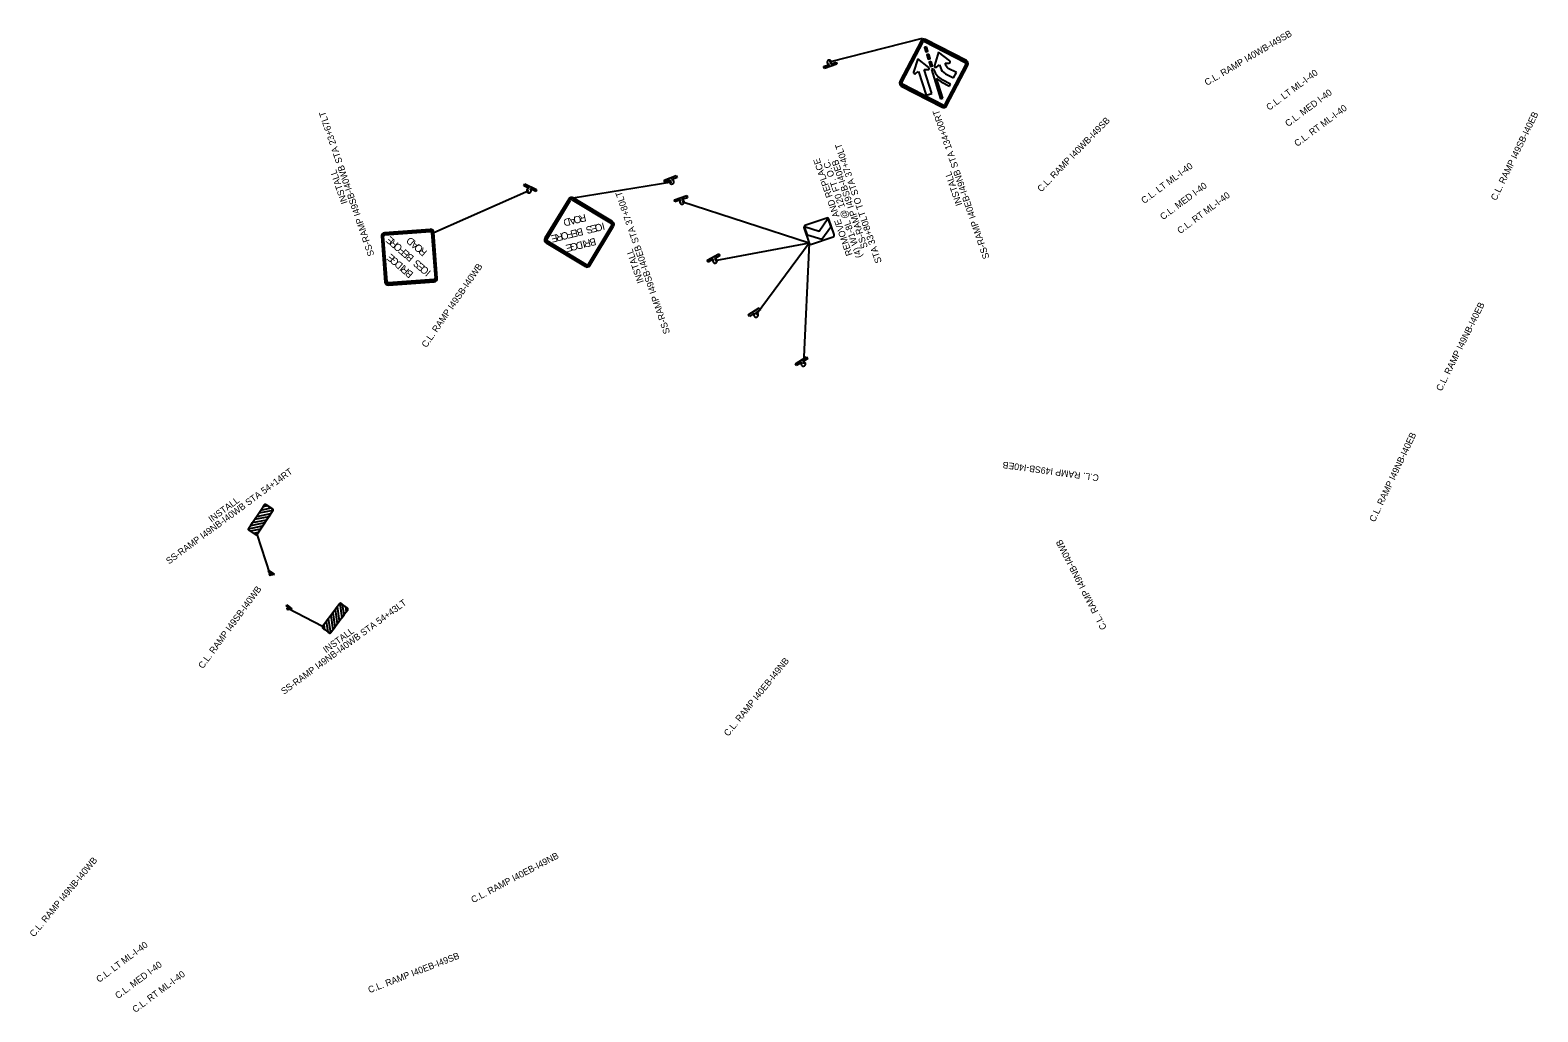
# Model space of a CAD drawing. Extents: x 639753 to 654136, y 407791 to 434220.
# Drawn here: x 643443 to 646199, y 424993 to 426786 of the extents above; entities that cross this region are included whole.
import ezdxf

# ---------------------------------------------------------------- set-up
doc = ezdxf.new("R2010")
doc.units = 0
for name, color, linetype in [('C-TRAF-SYMB', 7, 'Continuous'), ('P_SIGN_SR', 7, 'Continuous'), ('R_Anno_Text', 7, 'Continuous'), ('R_Dimension', 7, 'Continuous'), ('S_SIGN', 7, 'Continuous')]:
    doc.layers.add(name, color=color, linetype=linetype)

msp = doc.modelspace()

# ---------------------------------------------------------------- linework, layer by layer
at = {"layer": 'C-TRAF-SYMB'}
for p, q in [((644893.5, 426720.3), (644904.1, 426723.8)), ((644894.8, 426716.5), (644893.5, 426720.3)), ((644917.6, 426724.1), (644894.8, 426716.5)), ((644904.1, 426723.8), (644904.1, 426723.9)), ((644905.8, 426724.4), (644916.3, 426727.9)), ((644905.8, 426724.5), (644905.8, 426724.4)), ((644916.3, 426727.9), (644917.6, 426724.1)), ((644345.4, 426501.8), (644347.1, 426505.4)), ((644355.5, 426497.2), (644345.4, 426501.8)), ((644347.1, 426505.4), (644368.9, 426495.5)), ((644355.4, 426497.1), (644355.5, 426497.2)), ((644367.3, 426491.9), (644357.1, 426496.5)), ((644357.1, 426496.5), (644357.1, 426496.4)), ((644368.9, 426495.5), (644367.3, 426491.9)), ((644601.9, 426512.2), (644624.2, 426521.1)), ((644603.3, 426508.5), (644601.9, 426512.2)), ((644613.6, 426512.6), (644603.3, 426508.5)), ((644613.6, 426512.5), (644613.6, 426512.6)), ((644625.6, 426517.3), (644615.3, 426513.2)), ((644615.3, 426513.2), (644615.3, 426513.1)), ((644624.2, 426521.1), (644625.6, 426517.3)), ((644620.6, 426476.4), (644643.3, 426484.1)), ((644621.8, 426472.6), (644620.6, 426476.4)), ((644632.3, 426476.1), (644621.8, 426472.6)), ((644632.3, 426476), (644632.3, 426476.1)), ((644644.6, 426480.3), (644634, 426476.7)), ((644634, 426476.7), (644634.1, 426476.6)), ((644643.3, 426484.1), (644644.6, 426480.3)), ((644680.5, 426366.2), (644701.8, 426377.4)), ((644682.4, 426362.7), (644680.5, 426366.2)), ((644692.2, 426367.8), (644682.4, 426362.7)), ((644692.2, 426367.7), (644692.2, 426367.8)), ((644703.6, 426373.8), (644693.8, 426368.6)), ((644693.8, 426368.6), (644693.8, 426368.6)), ((644701.8, 426377.4), (644703.6, 426373.8)), ((644755.7, 426266.3), (644775.9, 426279.3)), ((644778, 426276), (644768.7, 426269.9)), ((644775.9, 426279.3), (644778, 426276)), ((644757.8, 426263), (644755.7, 426266.3)), ((644767.1, 426269), (644757.8, 426263)), ((644767.2, 426268.9), (644767.1, 426269)), ((644768.7, 426269.9), (644768.7, 426269.9)), ((644842.1, 426176.7), (644862.2, 426189.7)), ((644844.2, 426173.4), (644842.1, 426176.7)), ((644853.5, 426179.3), (644844.2, 426173.4)), ((644853.6, 426179.2), (644853.5, 426179.3)), ((644864.4, 426186.3), (644855, 426180.3)), ((644855, 426180.3), (644855.1, 426180.2)), ((644862.2, 426189.7), (644864.4, 426186.3)), ((643878, 425797.6), (643879.2, 425799.3)), ((643882.6, 425794.4), (643878, 425797.6)), ((643879.2, 425799.3), (643889, 425792.4)), ((643882.5, 425794.4), (643882.6, 425794.4)), ((643887.9, 425790.7), (643883.3, 425793.9)), ((643883.3, 425793.9), (643883.3, 425793.9)), ((643889, 425792.4), (643887.9, 425790.7)), ((643910.9, 425734.9), (643912.2, 425736.5)), ((643915.2, 425731.5), (643910.9, 425734.9)), ((643912.2, 425736.5), (643921.5, 425729)), ((643915.2, 425731.4), (643915.2, 425731.5)), ((643920.3, 425727.4), (643915.9, 425730.9)), ((643915.9, 425730.9), (643915.9, 425730.9)), ((643921.5, 425729), (643920.3, 425727.4))]:
    msp.add_line(p, q, dxfattribs=at)
for centre, radius, start, end in [((644903.7, 426727.9), 4, 18.2791, 275.9592), ((644903.7, 426727.9), 4, 302.1412, 18.2791), ((644354.7, 426493.2), 4, 155.6646, 53.3447), ((644354.7, 426493.2), 4, 79.5267, 155.6646), ((644616, 426509.2), 4, 125.4637, 201.6016), ((644616, 426509.2), 4, 201.6016, 99.2817), ((644634.5, 426472.6), 4, 122.4838, 198.6217), ((644634.5, 426472.6), 4, 198.6217, 96.3018), ((644694.9, 426364.7), 4, 131.6745, 207.8123), ((644694.9, 426364.7), 4, 207.8123, 105.4924), ((644770.1, 426266.1), 4, 136.6107, 212.7486), ((644770.1, 426266.1), 4, 212.7486, 110.4287), ((644856.5, 426176.5), 4, 136.6107, 212.7486), ((644856.5, 426176.5), 4, 212.7486, 110.4287), ((643881.8, 425792.5), 2, 145.0606, 42.7407), ((643881.8, 425792.5), 2, 68.9227, 145.0606), ((643914.3, 425729.6), 2, 141.2788, 38.9589), ((643914.3, 425729.6), 2, 65.141, 141.2788)]:
    msp.add_arc(centre, radius, start, end, dxfattribs=at)
at = {"layer": 'P_SIGN_SR'}
for p, q in [((643881.8, 425792.5), (643858, 425865.3)), ((643977.5, 425696.6), (643914.3, 425729.6))]:
    msp.add_line(p, q, dxfattribs=at)
for points in [[(643842.4, 425875.7), (643870.8, 425918.7)], [(643870.9, 425918.9), (643871.1, 425919.1), (643871.4, 425919.3), (643871.7, 425919.5), (643872, 425919.7), (643872.3, 425919.7), (643872.6, 425919.8), (643872.9, 425919.8), (643873.2, 425919.8), (643873.4, 425919.7), (643873.7, 425919.6), (643874.2, 425919.3), (643874.6, 425919.1), (643875, 425918.8), (643875.3, 425918.6), (643875.7, 425918.3), (643876.1, 425918), (643876.5, 425917.8), (643876.9, 425917.5), (643877.3, 425917.3), (643877.7, 425917), (643868.4, 425915.1), (643870.9, 425918.9)], [(643874.1, 425919.4), (643885.8, 425911.7)], [(643874.1, 425919.4), (643874.1, 425919.4), (643874.1, 425919.4)], [(643875.5, 425891.8), (643871.7, 425886), (643845.7, 425880.6), (643849.6, 425886.5), (643875.5, 425891.8)], [(643857.1, 425898), (643883.1, 425903.3), (643879.2, 425897.4), (643853.3, 425892.1), (643857.1, 425898)], [(643886.5, 425908.4), (643858.1, 425865.4)], [(643883.4, 425913.3), (643883.8, 425913), (643884.2, 425912.7), (643884.7, 425912.4), (643885.1, 425912.1), (643885.5, 425911.9), (643885.9, 425911.6), (643886.3, 425911.3), (643886.6, 425910.9), (643886.8, 425910.4), (643886.8, 425909.9), (643886.9, 425909.8), (643886.9, 425909.6), (643886.8, 425909.5), (643886.8, 425909.4), (643886.8, 425909.3), (643886.8, 425909.1), (643886.7, 425909), (643886.7, 425908.9), (643886.7, 425908.8), (643886.7, 425908.8), (643860.8, 425903.5), (643864.7, 425909.4), (643883.4, 425913.3)], [(643842.1, 425874.2), (643842, 425874.4), (643842.1, 425874.6), (643842.1, 425874.9), (643842.2, 425875.1), (643842.2, 425875.2), (643868, 425880.5), (643864.1, 425874.6), (643845.7, 425870.7), (643845.4, 425871), (643845, 425871.2), (643844.7, 425871.4), (643844.3, 425871.6), (643844, 425871.9), (643843.6, 425872.1), (643843.2, 425872.4), (643842.9, 425872.6), (643842.6, 425872.9), (643842.4, 425873.3), (643842.2, 425873.5), (643842.2, 425873.7), (643842.1, 425873.9), (643842.1, 425874.2)], [(643854.8, 425864.7), (643843.1, 425872.5)], [(643851.2, 425867.1), (643860.5, 425869), (643858, 425865.3), (643857.7, 425864.9), (643857.5, 425864.8), (643857.2, 425864.6), (643856.9, 425864.5), (643856.6, 425864.4), (643856.3, 425864.3), (643856, 425864.3), (643855.7, 425864.4), (643855.4, 425864.5), (643855.1, 425864.6), (643854.7, 425864.8), (643854.4, 425865), (643854, 425865.3), (643853.6, 425865.6), (643853.2, 425865.8), (643852.7, 425866.1), (643852.4, 425866.4), (643852, 425866.6), (643851.6, 425866.9), (643851.2, 425867.1)], [(644008.4, 425738.1), (643977.6, 425696.8)], [(643992.6, 425685.6), (644023.4, 425726.9)], [(644004.5, 425701.6), (644008.7, 425707.1), (644004.9, 425733.4), (644000.6, 425727.7), (644004.5, 425701.6)], [(644009.7, 425739), (644009.5, 425738.9), (644009.3, 425738.8), (644009, 425738.7), (644008.9, 425738.6), (644008.8, 425738.5), (644012.6, 425712.4), (644016.9, 425718.1), (644014.2, 425736.7), (644013.8, 425737), (644013.5, 425737.2), (644013.2, 425737.5), (644012.9, 425737.7), (644012.5, 425738), (644012.1, 425738.2), (644011.8, 425738.5), (644011.4, 425738.8), (644011.1, 425738.9), (644010.7, 425739), (644010.4, 425739.1), (644010.2, 425739.1), (644009.9, 425739.1), (644009.7, 425739)], [(644022.9, 425730.2), (644011.7, 425738.6)], [(644019.5, 425732.8), (644020.8, 425723.4), (644023.5, 425727), (644023.7, 425727.4), (644023.8, 425727.7), (644023.9, 425728), (644023.9, 425728.4), (644023.9, 425728.7), (644023.8, 425729), (644023.7, 425729.2), (644023.6, 425729.5), (644023.4, 425729.8), (644023.2, 425730), (644022.8, 425730.3), (644022.5, 425730.5), (644022.1, 425730.8), (644021.7, 425731.1), (644021.3, 425731.4), (644020.9, 425731.7), (644020.6, 425732), (644020.2, 425732.3), (644019.8, 425732.5), (644019.5, 425732.8)], [(643977.5, 425696.6), (643977.3, 425696.3), (643977.2, 425696.1), (643977.1, 425695.7), (643977.1, 425695.4), (643977.1, 425695.1), (643977.2, 425694.8), (643977.3, 425694.5), (643977.4, 425694.2), (643977.6, 425694), (643977.8, 425693.7), (643978.2, 425693.4), (643978.5, 425693.1), (643978.9, 425692.9), (643979.3, 425692.6), (643979.7, 425692.3), (643980, 425692), (643980.4, 425691.7), (643980.8, 425691.5), (643981.2, 425691.2), (643981.6, 425690.9), (643980.2, 425700.3), (643977.5, 425696.6)], [(643987, 425686.8), (643987.4, 425686.5), (643987.9, 425686.2), (643988.3, 425685.9), (643988.7, 425685.6), (643989.1, 425685.3), (643989.5, 425685), (643989.9, 425684.8), (643990.4, 425684.7), (643990.9, 425684.6), (643991.3, 425684.7), (643991.5, 425684.8), (643991.6, 425684.8), (643991.7, 425684.9), (643991.8, 425684.9), (643991.9, 425685), (643992, 425685), (643992.1, 425685.1), (643992.2, 425685.2), (643992.3, 425685.2), (643992.4, 425685.3), (643988.5, 425711.4), (643984.3, 425705.8), (643987, 425686.8)], [(643992.5, 425716.7), (643996.3, 425690.5), (644000.5, 425696.1), (643996.7, 425722.4), (643992.5, 425716.7)], [(643978.1, 425693.5), (643989.3, 425685.1)], [(643978.1, 425693.5), (643978.1, 425693.5), (643978.1, 425693.5)]]:
    msp.add_lwpolyline(points, dxfattribs=at)
for centre, start, end in [((643872.8, 425917.5), 56.5942, 146.5944), ((643884.5, 425909.7), 326.594, 56.5942), ((643844.4, 425874.4), 146.5944, 236.594), ((643856.1, 425866.7), 236.5943, 326.594), ((644010.3, 425736.7), 53.3115, 143.3112), ((644021.5, 425728.3), 323.3116, 53.3112), ((643979.5, 425695.4), 143.3112, 233.3114), ((643990.7, 425687), 233.3114, 323.3116)]:
    msp.add_arc(centre, 2.34, start, end, dxfattribs=at)
at = {"layer": 'R_Dimension'}
for p, q in [((645073.9, 426771), (644903.7, 426727.9)), ((644435.8, 426479.9), (644616, 426509.2)), ((644180.9, 426416.9), (644354.7, 426493.2)), ((644867.3, 426397.2), (644634.5, 426472.6)), ((644867.3, 426397.2), (644694.9, 426364.7)), ((644867.3, 426397.2), (644770.1, 426266.1)), ((644867.3, 426397.2), (644856.5, 426176.5))]:
    msp.add_line(p, q, dxfattribs=at)
at = {"layer": 'S_SIGN'}
for p, q in [((645071.8, 426767), (645033, 426692.5)), ((645154.4, 426730.7), (645079.9, 426769.5)), ((645103.8, 426746), (645096.2, 426721.6)), ((645124, 426730.3), (645103.8, 426746)), ((645065.7, 426734), (645058, 426709.6)), ((645085.9, 426718.3), (645065.7, 426734)), ((645094.5, 426715.8), (645090.6, 426714.6)), ((645094.9, 426714.2), (645094.5, 426715.8)), ((645099.6, 426719.1), (645105.3, 426723.1)), ((645105.3, 426723.1), (645106.9, 426718)), ((645117.4, 426721.3), (645115.8, 426726.4)), ((645115.8, 426726.4), (645122.6, 426726.3)), ((645118.1, 426648.1), (645156.9, 426722.6)), ((645136.2, 426708.8), (645121.3, 426716.6)), ((645061.5, 426707.1), (645067.1, 426711.1)), ((645067.1, 426711.1), (645080.8, 426667.4)), ((645077.6, 426714.4), (645084.5, 426714.3)), ((645091.3, 426670.7), (645077.6, 426714.4)), ((645090.6, 426714.6), (645107.4, 426661.1)), ((645111.3, 426662.3), (645099.8, 426698.6)), ((645108.6, 426692.2), (645123.5, 426684.4)), ((645125.3, 426688), (645110.4, 426695.8)), ((645116.2, 426706.8), (645131.1, 426699.1)), ((645123.5, 426684.4), (645125.3, 426688)), ((645131.1, 426699.1), (645136.2, 426708.8)), ((645035.5, 426684.4), (645110, 426645.6)), ((645080.8, 426667.4), (645091.3, 426670.7)), ((645107.4, 426661.1), (645111.3, 426662.3)), ((644427.6, 426477.9), (644384.1, 426406.1)), ((644507.6, 426436.5), (644435.8, 426479.9)), ((644899.1, 426443.1), (644859.4, 426429.4)), ((644885.1, 426419.2), (644901, 426442.1)), ((644912.7, 426412.8), (644902.9, 426441.2)), ((644174.4, 426422.4), (644090.7, 426416.2)), ((644187.1, 426333.2), (644180.9, 426416.9)), ((644466.2, 426356.4), (644509.6, 426428.2)), ((644857.5, 426425.6), (644867.3, 426397.2)), ((644858.5, 426427.5), (644885.1, 426419.2)), ((644906.4, 426426.5), (644890.5, 426403.6)), ((644085.2, 426409.7), (644091.5, 426326)), ((644386.1, 426397.8), (644457.9, 426354.4)), ((644890.5, 426403.6), (644863.8, 426411.9)), ((644871.1, 426395.4), (644910.8, 426409)), ((644097.9, 426320.5), (644181.6, 426326.8))]:
    msp.add_line(p, q, dxfattribs=at)
for points in [[(645073.1, 426766.3), (645034.3, 426691.8)], [(645036.5, 426690.6), (645075.3, 426765.1)], [(645073.1, 426766.3), (645073.1, 426766.3), (645073.1, 426766.3)], [(645078, 426766), (645152.5, 426727.1)], [(645081.8, 426755.8), (645078, 426754.6), (645080.4, 426747), (645084.2, 426748.2), (645081.8, 426755.8)], [(645153.7, 426729.3), (645079.2, 426768.2)], [(645086, 426742.5), (645082.2, 426741.3), (645084.6, 426733.6), (645088.5, 426734.8), (645086, 426742.5)], [(645090.3, 426729.1), (645086.4, 426727.9), (645088.8, 426720.3), (645092.7, 426721.5), (645090.3, 426729.1)], [(645153.4, 426724.4), (645114.5, 426649.9)], [(645116.8, 426648.8), (645155.6, 426723.3)], [(645153.7, 426729.3), (645153.7, 426729.3), (645153.7, 426729.3)], [(645111.8, 426649.1), (645037.4, 426687.9)], [(645036.2, 426685.7), (645110.7, 426646.9)], [(645036.2, 426685.7), (645036.2, 426685.7), (645036.2, 426685.7)], [(645116.8, 426648.8), (645116.8, 426648.8), (645116.8, 426648.8)], [(644429, 426477), (644385.5, 426405.2)], [(644387.5, 426404), (644431, 426475.8)], [(644429, 426477), (644429, 426477), (644429, 426477)], [(644433.7, 426476.5), (644505.5, 426433)], [(644506.7, 426435), (644434.9, 426478.5)], [(644863.8, 426411.9), (644858.5, 426427.5), (644885.1, 426419.2), (644901, 426442.1), (644906.4, 426426.5), (644890.5, 426403.6), (644863.8, 426411.9)], [(644174.6, 426420.8), (644090.8, 426414.5)], [(644091, 426412.2), (644174.7, 426418.5)], [(644174.6, 426420.8), (644174.6, 426420.8), (644174.6, 426420.8)], [(644176.9, 426416.6), (644183.1, 426332.9)], [(644185.5, 426333.1), (644179.2, 426416.8)], [(644506.2, 426430.3), (644462.8, 426358.5)], [(644464.8, 426357.3), (644508.2, 426429.1)], [(644506.7, 426435), (644506.7, 426435), (644506.7, 426435)], [(644086.8, 426409.9), (644093.1, 426326.2)], [(644086.8, 426409.9), (644086.8, 426409.9), (644086.8, 426409.9)], [(644095.4, 426326.3), (644089.2, 426410)], [(644387, 426399.3), (644458.8, 426355.8)], [(644387, 426399.3), (644387, 426399.3), (644387, 426399.3)], [(644460, 426357.8), (644388.2, 426401.3)], [(644464.8, 426357.3), (644464.8, 426357.3), (644464.8, 426357.3)], [(644181.3, 426330.8), (644097.6, 426324.5)], [(644185.5, 426333.1), (644185.5, 426333.1), (644185.5, 426333.1)], [(644097.8, 426322.2), (644181.5, 426328.4)], [(644097.8, 426322.2), (644097.8, 426322.2), (644097.8, 426322.2)]]:
    msp.add_lwpolyline(points, dxfattribs=at)
for centre, radius, start, end in [((645077.1, 426764.2), 6, 62.4666, 152.4664), ((645077.1, 426764.2), 4.5, 62.4666, 152.4664), ((645077.1, 426764.2), 2, 62.4666, 152.4664), ((645084.5, 426716.6), 2.25, 269.5824, 52.3142), ((645098.3, 426720.9), 2.25, 162.6192, 305.351), ((645125, 426723.7), 19, 197.4665, 242.4666), ((645125, 426723.7), 8, 197.4665, 242.4666), ((645122.7, 426728.6), 2.25, 269.5824, 52.3142), ((645151.6, 426725.4), 2, 332.4668, 62.4664), ((645151.6, 426725.4), 4.5, 332.4668, 62.4664), ((645151.6, 426725.4), 6, 332.4668, 62.4664), ((645038.3, 426689.7), 6, 152.4664, 242.4666), ((645038.3, 426689.7), 4.5, 152.4664, 242.4666), ((645038.3, 426689.7), 2, 152.4664, 242.4666), ((645060.2, 426708.9), 2.25, 162.6192, 305.351), ((645125, 426723.7), 31.5, 197.4665, 242.4666), ((645125, 426723.7), 35.5, 224.9278, 242.4666), ((645112.8, 426650.9), 6, 242.4666, 332.4668), ((645112.8, 426650.9), 4.5, 242.4666, 332.4668), ((645112.8, 426650.9), 2, 242.4666, 332.4668), ((644432.7, 426474.8), 6, 58.8254, 148.8256), ((644432.7, 426474.8), 4.33, 58.8254, 148.8256), ((644432.7, 426474.8), 2, 58.8254, 148.8256), ((644900.1, 426440.2), 3, 18.9552, 108.9554), ((644091.2, 426410.2), 6, 94.2816, 184.2812), ((644091.2, 426410.2), 4.33, 94.2816, 184.2812), ((644091.2, 426410.2), 2, 94.2816, 184.2812), ((644174.9, 426416.5), 6, 4.2813, 94.2816), ((644174.9, 426416.5), 4.33, 4.2813, 94.2816), ((644174.9, 426416.5), 2, 4.2813, 94.2816), ((644504.5, 426431.3), 2, 328.8252, 58.8254), ((644504.5, 426431.3), 4.33, 328.8252, 58.8254), ((644504.5, 426431.3), 6, 328.8252, 58.8254), ((644860.4, 426426.6), 3, 108.9552, 198.9554), ((644909.9, 426411.9), 3, 288.955, 18.9552), ((644389.2, 426403), 6, 148.8256, 238.8252), ((644389.2, 426403), 4.33, 148.8256, 238.8252), ((644389.2, 426403), 2, 148.8256, 238.8252), ((644870.1, 426398.2), 3, 198.9554, 288.955), ((644461.1, 426359.5), 4.33, 238.8254, 328.8252), ((644461.1, 426359.5), 2, 238.8254, 328.8252), ((644181.1, 426332.8), 2, 274.2811, 4.2813), ((644181.1, 426332.8), 4.33, 274.2811, 4.2813), ((644181.1, 426332.8), 6, 274.2811, 4.2813), ((644461.1, 426359.5), 6, 238.8254, 328.8252), ((644097.4, 426326.5), 6, 184.2814, 274.2811), ((644097.4, 426326.5), 4.33, 184.2814, 274.2811), ((644097.4, 426326.5), 2, 184.2814, 274.2811)]:
    msp.add_arc(centre, radius, start, end, dxfattribs=at)

# ---------------------------------------------------------------- texts
at = {"layer": 'R_Anno_Text'}
for s, rotation, p in [('C.L. RAMP I40WB-I49SB', 30.5136, (645594.2, 426684.5)), ('C.L. LT ML-I-40', 36.6906, (645708.1, 426639)), ('C.L. MED I-40', 36.6906, (645742.6, 426609.3)), ('SS-RAMP I49SB-I40WB STA 23+67LT', 108.9552, (644072.4, 426375.7)), ('SS-RAMP I40EB-I49NB STA 134+00RT', 108.9552, (645196.9, 426370.7)), ('C.L. RT ML-I-40', 36.6906, (645759.3, 426572.9)), ('C.L. RAMP I49SB-I40EB', 64.1373, (646123.1, 426474)), ('C.L. RAMP I40WB-I49SB', 45.9039, (645291.4, 426489.8)), ('REMOVE AND REPLACE', 108.9552, (644946.5, 426376.4)), ('(4) W1-8L @ 120 FT. O.C.', 108.9552, (644964.2, 426372.4)), ('STA 33+80LT TO STA 37+40LT', 108.9552, (645000, 426362.9)), ('INSTALL', 108.9552, (644023.4, 426471)), ('SS-RAMP I49SB-I40EB', 108.9552, (644974.5, 426389.9)), ('INSTALL', 108.9552, (645147.2, 426467.8)), ('C.L. LT ML-I-40', 36.6906, (645479.5, 426468.6)), ('C.L. MED I-40', 36.6906, (645514, 426439)), ('SS-RAMP I49SB-I40EB STA 37+80LT', 108.9552, (644613, 426233.7)), ('C.L. RT ML-I-40', 36.6906, (645545.4, 426413.5)), ('INSTALL', 108.9552, (644564.9, 426326.3)), ('C.L. RAMP I49SB-I40WB', 55.4015, (644167.3, 426205.2)), ('C.L. RAMP I49NB-I40EB', 63.6932, (646023.2, 426125.7)), ('C.L. RAMP I49NB-I40EB', 64.7041, (645901.1, 425886.6)), ('SS-RAMP I49NB-I40WB STA 54+14RT', 36.3915, (643696.8, 425809.9)), ('C.L. RAMP I49SB-I40EB', 172.137, (645397.4, 425973.8)), ('INSTALL', 36.3915, (643774.5, 425886.3)), ('C.L. RAMP I49NB-I40WB', 117.1756, (645411.5, 425694.2)), ('C.L. RAMP I49SB-I40WB', 53.6373, (643758.8, 425618.6)), ('SS-RAMP I49NB-I40WB STA 54+43LT', 36.3915, (643907.1, 425571.8)), ('INSTALL', 36.3915, (643984, 425647.6)), ('C.L. RAMP I40EB-I49NB', 51.0694, (644719.2, 425495)), ('C.L. RAMP I40EB-I49NB', 27.778, (644252.8, 425191)), ('C.L. RAMP I49NB-I40WB', 50.3729, (643450, 425128.3)), ('C.L. LT ML-I-40', 36.6906, (643569.2, 425045.3)), ('C.L. RAMP I40EB-I49SB', 21.0971, (644063.4, 425026.5)), ('C.L. MED I-40', 36.6906, (643603.7, 425015.6)), ('C.L. RT ML-I-40', 36.6906, (643635.2, 424990.2))]:
    msp.add_text(s, height=12, rotation=rotation, dxfattribs=at).set_placement(p)
at = {"layer": 'S_SIGN'}
for s, rotation, p in [('D', 193.8254, (644428.9, 426443.6)), ('A', 193.8254, (644439, 426446.1)), ('O', 193.8254, (644448.5, 426448.4)), ('R', 193.8254, (644457.6, 426450.7)), ('E', 193.8254, (644405.4, 426413.8)), ('R', 193.8254, (644415.1, 426416.2)), ('O', 193.8254, (644425.2, 426418.7)), ('F', 193.8254, (644433.8, 426420.8)), ('E', 193.8254, (644442.3, 426422.9)), ('B', 193.8254, (644452, 426425.3)), ('S', 193.8254, (644469.4, 426429.6)), ('E', 193.8254, (644478, 426431.7)), ('C', 193.8254, (644487.2, 426433.9)), ('I', 193.8254, (644491.6, 426435)), ('E', 139.2814, (644109.4, 426403.3)), ('R', 139.2814, (644116.9, 426396.8)), ('O', 139.2814, (644124.8, 426390)), ('F', 139.2814, (644131.5, 426384.3)), ('E', 139.2814, (644138.2, 426378.5)), ('D', 139.2814, (644147.3, 426401.4)), ('A', 139.2814, (644155.2, 426394.7)), ('O', 139.2814, (644162.6, 426388.3)), ('R', 139.2814, (644169.7, 426382.2)), ('E', 193.8254, (644432.5, 426396.5)), ('G', 193.8254, (644442.3, 426398.9)), ('D', 193.8254, (644451.6, 426401.1)), ('I', 193.8254, (644456.1, 426402.3)), ('R', 193.8254, (644465.9, 426404.7)), ('B', 193.8254, (644475.6, 426407.1)), ('E', 139.2814, (644111, 426371.2)), ('G', 139.2814, (644118.6, 426364.6)), ('D', 139.2814, (644125.8, 426358.4)), ('I', 139.2814, (644129.4, 426355.3)), ('B', 139.2814, (644145.8, 426372)), ('S', 139.2814, (644159.4, 426360.3)), ('E', 139.2814, (644166, 426354.5)), ('R', 139.2814, (644137, 426348.8)), ('B', 139.2814, (644144.6, 426342.2)), ('C', 139.2814, (644173.2, 426348.4)), ('I', 139.2814, (644176.7, 426345.4))]:
    msp.add_text(s, height=13.3, rotation=rotation, dxfattribs=at).set_placement(p)

doc.saveas('drawing.dxf')
